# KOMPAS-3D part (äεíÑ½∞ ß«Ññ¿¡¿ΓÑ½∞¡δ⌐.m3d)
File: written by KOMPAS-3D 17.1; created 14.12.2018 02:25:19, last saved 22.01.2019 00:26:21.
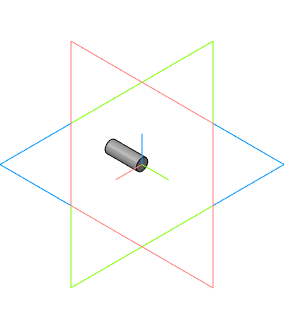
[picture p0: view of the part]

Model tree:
1. Эскиз:1
2. Операция выдавливания:1
     Расстояние 2 = 11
